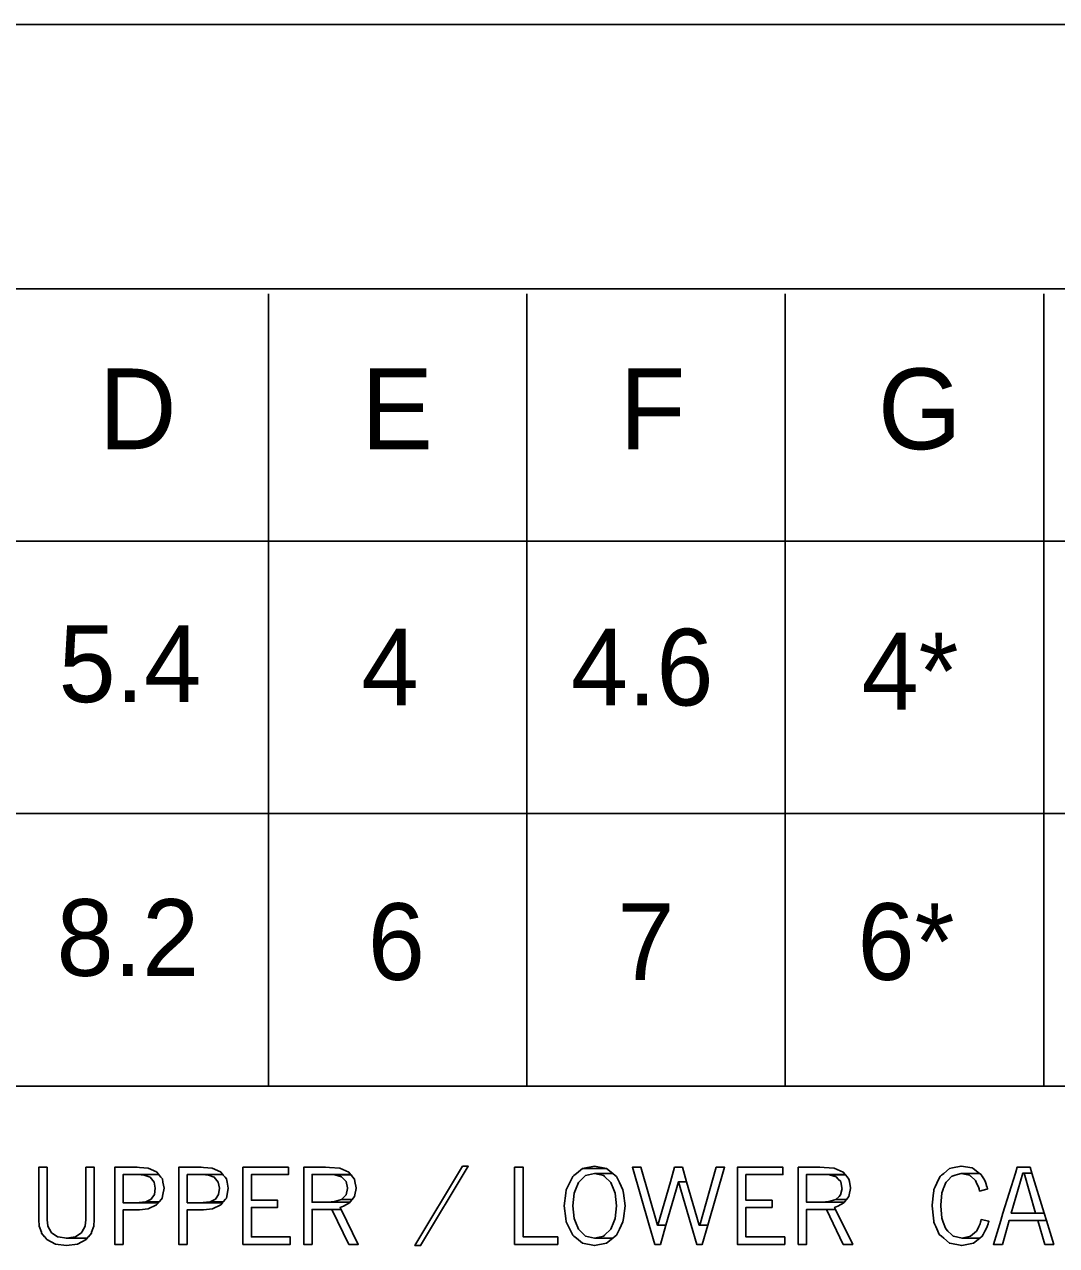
# Model space of a CAD drawing. Extents: x 0.013 to 0.187, y -0.092 to 0.261.
# Drawn here: x 0.06135 to 0.09331, y 0.0569 to 0.09473 of the extents above; entities that cross this region are included whole.
import ezdxf

# ---------------------------------------------------------------- set-up
doc = ezdxf.new("R2010")
doc.units = 0
doc.layers.add('3', color=7, linetype='Continuous')

msp = doc.modelspace()

# ---------------------------------------------------------------- linework, layer by layer
at = {"layer": '3'}
for p, q in [((0.032451, 0.094728), (0.186512, 0.094728)), ((0.186512, 0.086538), (0.032451, 0.086538)), ((0.068908, 0.086386), (0.068908, 0.061842)), ((0.076908, 0.086386), (0.076908, 0.061842)), ((0.084908, 0.086386), (0.084908, 0.061842)), ((0.092908, 0.086386), (0.092908, 0.061842)), ((0.032384, 0.078726), (0.186512, 0.078726)), ((0.032451, 0.070284), (0.186512, 0.070284)), ((0.032519, 0.061842), (0.186512, 0.061842))]:
    msp.add_line(p, q, dxfattribs=at)
for points in [[(0.062314, 0.056949), (0.062653, 0.056904), (0.062992, 0.056949), (0.06326, 0.057092), (0.063291, 0.05713), (0.062653, 0.05713), (0.062395, 0.057175), (0.062378, 0.057178), (0.062213, 0.05729), (0.062179, 0.057313), (0.062177, 0.057314), (0.062078, 0.057506), (0.062078, 0.057508), (0.062077, 0.057513), (0.062077, 0.057514), (0.062055, 0.057706), (0.062054, 0.057746), (0.062054, 0.057749), (0.062054, 0.057834), (0.062054, 0.059329), (0.061794, 0.059329), (0.061794, 0.057834), (0.061794, 0.057749), (0.061794, 0.057746), (0.061797, 0.057706), (0.061809, 0.057514), (0.061809, 0.057513), (0.06181, 0.057508), (0.061811, 0.057506), (0.061875, 0.057314), (0.061875, 0.057313), (0.061883, 0.05729), (0.061975, 0.057178), (0.061978, 0.057175), (0.062015, 0.05713), (0.062046, 0.057092)], [(0.062924, 0.057175), (0.062653, 0.05713), (0.063291, 0.05713), (0.063328, 0.057175), (0.063331, 0.057178), (0.063423, 0.05729), (0.063431, 0.057313), (0.063431, 0.057314), (0.063496, 0.057506), (0.063495, 0.057506), (0.063496, 0.057508), (0.063496, 0.057508), (0.063498, 0.057513), (0.063498, 0.057514), (0.063509, 0.057706), (0.063512, 0.057746), (0.063512, 0.057749), (0.063512, 0.057834), (0.063512, 0.059329), (0.063253, 0.059329), (0.063253, 0.057834), (0.063252, 0.057749), (0.063252, 0.057746), (0.063252, 0.057706), (0.063232, 0.057514), (0.063232, 0.057513), (0.063231, 0.057508), (0.06323, 0.057506), (0.063133, 0.057314), (0.063132, 0.057313), (0.063097, 0.05729), (0.062928, 0.057178)], [(0.064146, 0.058008), (0.064146, 0.056942), (0.064403, 0.056942), (0.064403, 0.058008), (0.064914, 0.058008), (0.065186, 0.058041), (0.065444, 0.058161), (0.065501, 0.058232), (0.064404, 0.058232), (0.064404, 0.058233), (0.064404, 0.058259), (0.064404, 0.058344), (0.064404, 0.058377), (0.064404, 0.058485), (0.064404, 0.058679), (0.064404, 0.05868), (0.064404, 0.05887), (0.064404, 0.058969), (0.064404, 0.059021), (0.064404, 0.059088), (0.064404, 0.059104), (0.064404, 0.059105), (0.06551, 0.059105), (0.065439, 0.059191), (0.065182, 0.059301), (0.064915, 0.059327), (0.064838, 0.059329), (0.064146, 0.059329), (0.064146, 0.059327), (0.064146, 0.059301), (0.064146, 0.059191), (0.064146, 0.059105), (0.064146, 0.059104), (0.064146, 0.059088), (0.064146, 0.059021), (0.064146, 0.058969), (0.064146, 0.05887), (0.064146, 0.05868), (0.064146, 0.058679), (0.064146, 0.058485), (0.064146, 0.058377), (0.064146, 0.058344), (0.064146, 0.058259), (0.064146, 0.058233), (0.064146, 0.058232), (0.064146, 0.058161), (0.064146, 0.058041)], [(0.065277, 0.058344), (0.065111, 0.058259), (0.065523, 0.058259), (0.065592, 0.058344), (0.065618, 0.058377), (0.065638, 0.058485), (0.065673, 0.058679), (0.065673, 0.05868), (0.065639, 0.05887), (0.065622, 0.058969), (0.065579, 0.059021), (0.065524, 0.059088), (0.065511, 0.059104), (0.06551, 0.059105), (0.064788, 0.059105), (0.064877, 0.059104), (0.065063, 0.059088), (0.06524, 0.059021), (0.065284, 0.058969), (0.065369, 0.05887), (0.065403, 0.05868), (0.065403, 0.058679), (0.065375, 0.058485), (0.0653, 0.058377)], [(0.066131, 0.058008), (0.066131, 0.056942), (0.066388, 0.056942), (0.066388, 0.058008), (0.066899, 0.058008), (0.067171, 0.058041), (0.067429, 0.058161), (0.067486, 0.058232), (0.06639, 0.058232), (0.06639, 0.058233), (0.06639, 0.058259), (0.06639, 0.058344), (0.06639, 0.058377), (0.06639, 0.058485), (0.06639, 0.058679), (0.06639, 0.05868), (0.06639, 0.05887), (0.06639, 0.058969), (0.06639, 0.059021), (0.06639, 0.059088), (0.06639, 0.059104), (0.06639, 0.059105), (0.067495, 0.059105), (0.067424, 0.059191), (0.067168, 0.059301), (0.0669, 0.059327), (0.066823, 0.059329), (0.066131, 0.059329), (0.066131, 0.059327), (0.066131, 0.059301), (0.066131, 0.059191), (0.066131, 0.059105), (0.066131, 0.059104), (0.066131, 0.059088), (0.066131, 0.059021), (0.066131, 0.058969), (0.066131, 0.05887), (0.066131, 0.05868), (0.066131, 0.058679), (0.066131, 0.058485), (0.066131, 0.058377), (0.066131, 0.058344), (0.066131, 0.058259), (0.066131, 0.058233), (0.066131, 0.058232), (0.066131, 0.058161), (0.066131, 0.058041)], [(0.067262, 0.058344), (0.067097, 0.058259), (0.067508, 0.058259), (0.067577, 0.058344), (0.067604, 0.058377), (0.067623, 0.058485), (0.067659, 0.058679), (0.067658, 0.05868), (0.067625, 0.05887), (0.067607, 0.058969), (0.067564, 0.059021), (0.067509, 0.059088), (0.067496, 0.059104), (0.067495, 0.059105), (0.066774, 0.059105), (0.066862, 0.059104), (0.067048, 0.059088), (0.067226, 0.059021), (0.06727, 0.058969), (0.067354, 0.05887), (0.067388, 0.05868), (0.067388, 0.058679), (0.06736, 0.058485), (0.067285, 0.058377)], [(0.068117, 0.057172), (0.068117, 0.056942), (0.06958, 0.056942), (0.06958, 0.057172), (0.068379, 0.057172), (0.068379, 0.058085), (0.06919, 0.058085), (0.06919, 0.058306), (0.068379, 0.058306), (0.068379, 0.059103), (0.069524, 0.059103), (0.069524, 0.059329), (0.068117, 0.059329), (0.068117, 0.059103), (0.068117, 0.058306), (0.068117, 0.058085)], [(0.069999, 0.058024), (0.069999, 0.056942), (0.070258, 0.056942), (0.070258, 0.058024), (0.071156, 0.058024), (0.071126, 0.058086), (0.071228, 0.058122), (0.071415, 0.058228), (0.071429, 0.058246), (0.070258, 0.058246), (0.070258, 0.058249), (0.070258, 0.058264), (0.070258, 0.058332), (0.070258, 0.058428), (0.070258, 0.058472), (0.070258, 0.058676), (0.070258, 0.058696), (0.070258, 0.058887), (0.070258, 0.058964), (0.070258, 0.059034), (0.070258, 0.059093), (0.070258, 0.059104), (0.070258, 0.059106), (0.071451, 0.059106), (0.071391, 0.059179), (0.071115, 0.059298), (0.070798, 0.059326), (0.070669, 0.059329), (0.069999, 0.059329), (0.069999, 0.059326), (0.069999, 0.059298), (0.069999, 0.059179), (0.069999, 0.059106), (0.069999, 0.059104), (0.069999, 0.059093), (0.069999, 0.059034), (0.069999, 0.058964), (0.069999, 0.058887), (0.069999, 0.058696), (0.069999, 0.058676), (0.069999, 0.058472), (0.069999, 0.058428), (0.069999, 0.058332), (0.069999, 0.058264), (0.069999, 0.058249), (0.069999, 0.058246), (0.069999, 0.058228), (0.069999, 0.058122), (0.069999, 0.058086)], [(0.070777, 0.059104), (0.070965, 0.059093), (0.071463, 0.059093), (0.071453, 0.059104), (0.071453, 0.059104), (0.071451, 0.059106), (0.070666, 0.059106)], [(0.071264, 0.058428), (0.071165, 0.058332), (0.071496, 0.058332), (0.07157, 0.058428), (0.071579, 0.058472), (0.071618, 0.058676), (0.071622, 0.058696), (0.071585, 0.058887), (0.07157, 0.058964), (0.071512, 0.059034), (0.071463, 0.059093), (0.070964, 0.059093), (0.071172, 0.059034), (0.071239, 0.058964), (0.071314, 0.058887), (0.071351, 0.058696), (0.071355, 0.058676), (0.07131, 0.058472)], [(0.074909, 0.059363), (0.073442, 0.056903), (0.073617, 0.056903), (0.075092, 0.059363)], [(0.076527, 0.057172), (0.076527, 0.056942), (0.077864, 0.056942), (0.077864, 0.057172), (0.076797, 0.057172), (0.076797, 0.059329), (0.076527, 0.059329)], [(0.078634, 0.05698), (0.079005, 0.056903), (0.079376, 0.05698), (0.079565, 0.057133), (0.079004, 0.057133), (0.078723, 0.057197), (0.078694, 0.057225), (0.078501, 0.057409), (0.078411, 0.057637), (0.078371, 0.057738), (0.078329, 0.058135), (0.078371, 0.058532), (0.078411, 0.058633), (0.078501, 0.058861), (0.078694, 0.059045), (0.078723, 0.059073), (0.079004, 0.059138), (0.079565, 0.059138), (0.079376, 0.05929), (0.078634, 0.05929), (0.078445, 0.059138), (0.078365, 0.059073), (0.078331, 0.059045), (0.07824, 0.058861), (0.078127, 0.058633), (0.078114, 0.058532), (0.078062, 0.058135), (0.078114, 0.057738), (0.078127, 0.057637), (0.07824, 0.057409), (0.078331, 0.057225), (0.078365, 0.057197), (0.078445, 0.057133)], [(0.079005, 0.059367), (0.078634, 0.05929), (0.079376, 0.05929)], [(0.079286, 0.057197), (0.079004, 0.057133), (0.079565, 0.057133), (0.079645, 0.057197), (0.079645, 0.057197), (0.079679, 0.057225), (0.07977, 0.057409), (0.079883, 0.057637), (0.079896, 0.057738), (0.079948, 0.058135), (0.079896, 0.058532), (0.079883, 0.058633), (0.07977, 0.058861), (0.079679, 0.059045), (0.079645, 0.059073), (0.079645, 0.059073), (0.079565, 0.059138), (0.079004, 0.059138), (0.079286, 0.059073), (0.079315, 0.059045), (0.079507, 0.058861), (0.079597, 0.058633), (0.079637, 0.058532), (0.079679, 0.058135), (0.079637, 0.057738), (0.079597, 0.057637), (0.079507, 0.057409), (0.079315, 0.057225)], [(0.080697, 0.057538), (0.08087, 0.056942), (0.081041, 0.056942), (0.081213, 0.057538), (0.080948, 0.057538), (0.08044, 0.059329), (0.080175, 0.059329)], [(0.081352, 0.058879), (0.080965, 0.057538), (0.081213, 0.057538), (0.081603, 0.058879), (0.081854, 0.058879), (0.081724, 0.059329), (0.081482, 0.059329)], [(0.082766, 0.059329), (0.082258, 0.057538), (0.082509, 0.057538), (0.083031, 0.059329)], [(0.083426, 0.057172), (0.083426, 0.056942), (0.084889, 0.056942), (0.084889, 0.057172), (0.083688, 0.057172), (0.083688, 0.058085), (0.0845, 0.058085), (0.0845, 0.058306), (0.083688, 0.058306), (0.083688, 0.059103), (0.084833, 0.059103), (0.084833, 0.059329), (0.083426, 0.059329), (0.083426, 0.059103), (0.083426, 0.058306), (0.083426, 0.058085)], [(0.085308, 0.058024), (0.085308, 0.056942), (0.085568, 0.056942), (0.085568, 0.058024), (0.086466, 0.058024), (0.086435, 0.058086), (0.086538, 0.058122), (0.086725, 0.058228), (0.086739, 0.058246), (0.085568, 0.058246), (0.085568, 0.058249), (0.085568, 0.058264), (0.085568, 0.058332), (0.085568, 0.058428), (0.085568, 0.058472), (0.085568, 0.058676), (0.085568, 0.058696), (0.085568, 0.058887), (0.085568, 0.058964), (0.085568, 0.059034), (0.085568, 0.059093), (0.085568, 0.059104), (0.085568, 0.059106), (0.086761, 0.059106), (0.0867, 0.059179), (0.086425, 0.059298), (0.086108, 0.059326), (0.085979, 0.059329), (0.085308, 0.059329), (0.085308, 0.059326), (0.085308, 0.059298), (0.085308, 0.059179), (0.085308, 0.059106), (0.085308, 0.059104), (0.085308, 0.059093), (0.085308, 0.059034), (0.085308, 0.058964), (0.085308, 0.058887), (0.085308, 0.058696), (0.085308, 0.058676), (0.085308, 0.058472), (0.085308, 0.058428), (0.085308, 0.058332), (0.085308, 0.058264), (0.085308, 0.058249), (0.085308, 0.058246), (0.085308, 0.058228), (0.085308, 0.058122), (0.085308, 0.058086)], [(0.086086, 0.059104), (0.086274, 0.059093), (0.086772, 0.059093), (0.086763, 0.059104), (0.086762, 0.059104), (0.086761, 0.059106), (0.085976, 0.059106)], [(0.086574, 0.058428), (0.086474, 0.058332), (0.086805, 0.058332), (0.08688, 0.058428), (0.086888, 0.058472), (0.086927, 0.058676), (0.086932, 0.058696), (0.086895, 0.058887), (0.08688, 0.058964), (0.086821, 0.059034), (0.086772, 0.059093), (0.086274, 0.059093), (0.086482, 0.059034), (0.086549, 0.058964), (0.086623, 0.058887), (0.08666, 0.058696), (0.086664, 0.058676), (0.086619, 0.058472)], [(0.090003, 0.056975), (0.090371, 0.056904), (0.090735, 0.056975), (0.090739, 0.056978), (0.09093, 0.057131), (0.090381, 0.057131), (0.090114, 0.05719), (0.090111, 0.057191), (0.09011, 0.057192), (0.090109, 0.057192), (0.090051, 0.057249), (0.090051, 0.057249), (0.089945, 0.057355), (0.089875, 0.057423), (0.089849, 0.057494), (0.089819, 0.057576), (0.089798, 0.057633), (0.089788, 0.057658), (0.089754, 0.057751), (0.089723, 0.058135), (0.089722, 0.058158), (0.089758, 0.058539), (0.089777, 0.058592), (0.089798, 0.058651), (0.0898, 0.058656), (0.089824, 0.058722), (0.089867, 0.058841), (0.089888, 0.058864), (0.089938, 0.058915), (0.090068, 0.059051), (0.090074, 0.059057), (0.090171, 0.059087), (0.090242, 0.059108), (0.090242, 0.059108), (0.09035, 0.059141), (0.090923, 0.059141), (0.090723, 0.059287), (0.090723, 0.059287), (0.090694, 0.059308), (0.090352, 0.059367), (0.090351, 0.059367), (0.090084, 0.059308), (0.089987, 0.059287), (0.089813, 0.059141), (0.089774, 0.059108), (0.089748, 0.059087), (0.089713, 0.059057), (0.089706, 0.059051), (0.08964, 0.058915), (0.089615, 0.058864), (0.089604, 0.058841), (0.089546, 0.058722), (0.089514, 0.058656), (0.089512, 0.058651), (0.089505, 0.058592), (0.089499, 0.058539), (0.089455, 0.058158), (0.089453, 0.058135), (0.089493, 0.057751), (0.089503, 0.057658), (0.089506, 0.057633), (0.089531, 0.057576), (0.089568, 0.057494), (0.089599, 0.057423), (0.08963, 0.057355), (0.089677, 0.057249), (0.089743, 0.057192), (0.089745, 0.057191), (0.089745, 0.05719), (0.089812, 0.057131), (0.089987, 0.056978)], [(0.09091, 0.058651), (0.090925, 0.058592), (0.091152, 0.058651), (0.091173, 0.058656), (0.091154, 0.058722), (0.091153, 0.058722), (0.091118, 0.058841), (0.091111, 0.058864), (0.091081, 0.058915), (0.091002, 0.059051), (0.091002, 0.059051), (0.090998, 0.059057), (0.090981, 0.059087), (0.090969, 0.059108), (0.090923, 0.059141), (0.09035, 0.059141), (0.090507, 0.059108), (0.09061, 0.059087), (0.090642, 0.059057), (0.090649, 0.059051), (0.090797, 0.058915), (0.090822, 0.058864), (0.090833, 0.058841), (0.090891, 0.058722), (0.090908, 0.058656)], [(0.09158, 0.057685), (0.091352, 0.056942), (0.09163, 0.056942), (0.091843, 0.057685), (0.092993, 0.057685), (0.092925, 0.057906), (0.091906, 0.057906), (0.092264, 0.059149), (0.092542, 0.059149), (0.092487, 0.059329), (0.092086, 0.059329), (0.092031, 0.059149), (0.091648, 0.057906)], [(0.092299, 0.059149), (0.092656, 0.057906), (0.092925, 0.057906), (0.092542, 0.059149)], [(0.081992, 0.057538), (0.082165, 0.056942), (0.082336, 0.056942), (0.082509, 0.057538), (0.082241, 0.057538), (0.081854, 0.058879), (0.081603, 0.058879)], [(0.064901, 0.058233), (0.064807, 0.058232), (0.065501, 0.058232), (0.065502, 0.058233), (0.065523, 0.058259), (0.065111, 0.058259)], [(0.066887, 0.058233), (0.066793, 0.058232), (0.067486, 0.058232), (0.067487, 0.058233), (0.067508, 0.058259), (0.067096, 0.058259)], [(0.070743, 0.058249), (0.070657, 0.058246), (0.071429, 0.058246), (0.071432, 0.058249), (0.071444, 0.058264), (0.071496, 0.058332), (0.071164, 0.058332), (0.070947, 0.058264)], [(0.086053, 0.058249), (0.085966, 0.058246), (0.086739, 0.058246), (0.086741, 0.058249), (0.086753, 0.058264), (0.086805, 0.058332), (0.086474, 0.058332), (0.086257, 0.058264)], [(0.070872, 0.058024), (0.071395, 0.056942), (0.071686, 0.056942), (0.071156, 0.058024)], [(0.086182, 0.058024), (0.086705, 0.056942), (0.086996, 0.056942), (0.086466, 0.058024)], [(0.090639, 0.05719), (0.090381, 0.057131), (0.09093, 0.057131), (0.091004, 0.05719), (0.091005, 0.057191), (0.091004, 0.057191), (0.091007, 0.057192), (0.091036, 0.057249), (0.091091, 0.057355), (0.091127, 0.057423), (0.091163, 0.057494), (0.091187, 0.057576), (0.091203, 0.057633), (0.091211, 0.057658), (0.090972, 0.057711), (0.090959, 0.057658), (0.090953, 0.057633), (0.090939, 0.057576), (0.090899, 0.057494), (0.090865, 0.057423), (0.090832, 0.057355), (0.090709, 0.057249), (0.090642, 0.057192), (0.09064, 0.057191)], [(0.09273, 0.057685), (0.092944, 0.056942), (0.093222, 0.056942), (0.092993, 0.057685)]]:
    msp.add_lwpolyline(points, close=True, dxfattribs=at)

# ---------------------------------------------------------------- texts
for s, height, p in [('D', 0.0025, (0.06365, 0.081571)), ('E', 0.0025, (0.071775, 0.081571)), ('F', 0.0025, (0.079775, 0.081571)), ('G', 0.0025, (0.087775, 0.081571)), ('5.4', 0.0023752, (0.062408, 0.073736)), ('4.6', 0.0023752, (0.078269, 0.073633)), ('4', 0.002375, (0.071786, 0.073633)), ('4*', 0.0023752, (0.08727, 0.073508)), ('8.2', 0.0023752, (0.062346, 0.065258)), ('6', 0.002375, (0.071984, 0.065133)), ('7', 0.002375, (0.079708, 0.065133)), ('6*', 0.0023752, (0.087145, 0.065133))]:
    msp.add_text(s, height=height, dxfattribs=at).set_placement(p)

doc.saveas('drawing.dxf')
